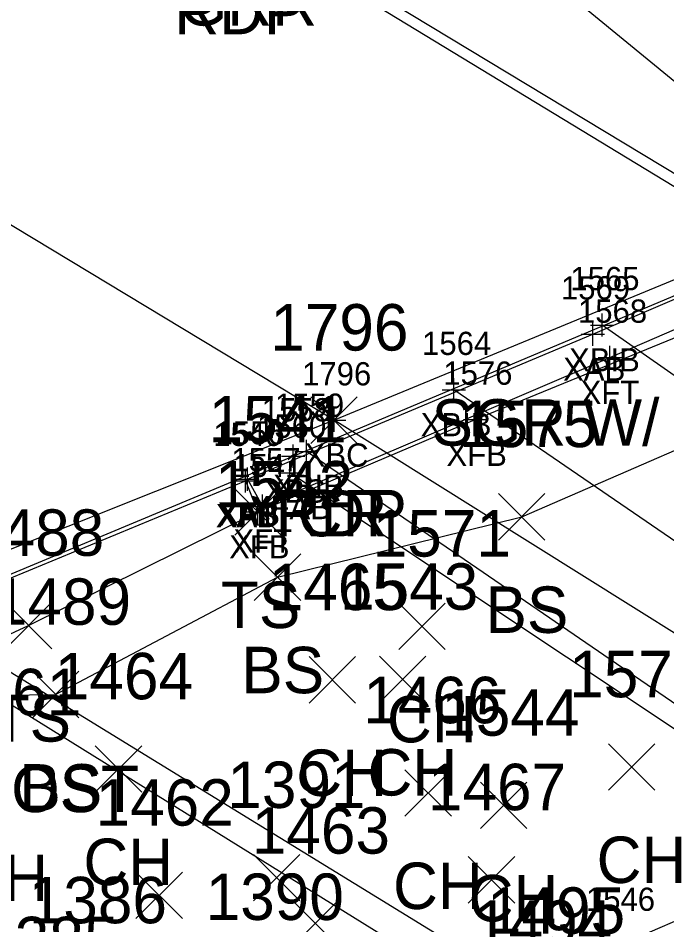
# Model space of a CAD drawing. Extents: x 1537342 to 1542195, y 163002 to 168596.
# Drawn here: x 1541772.7 to 1541800.63, y 163314.55 to 163353.59 of the extents above; entities that cross this region are included whole.
import ezdxf

# ---------------------------------------------------------------- set-up
doc = ezdxf.new("R2010")
doc.units = 0
for name, color, linetype in [('B_A', 7, 'Continuous'), ('B_I', 7, 'Continuous'), ('B_TIC', 7, 'Continuous'), ('BB', 7, 'Continuous'), ('BELB', 7, 'Continuous'), ('BF', 7, 'Continuous'), ('BFT', 7, 'Continuous'), ('BSE', 7, 'Continuous'), ('BSUBM', 7, 'Continuous'), ('L_A', 7, 'Continuous'), ('L_I', 7, 'Continuous'), ('L_TIC', 7, 'Continuous'), ('LELB', 7, 'Continuous'), ('P_A', 7, 'Continuous'), ('P_I', 7, 'Continuous'), ('P_TIC', 7, 'Continuous'), ('PET', 7, 'Continuous'), ('PRC', 7, 'Continuous'), ('R_A', 7, 'Continuous'), ('R_C', 7, 'Continuous'), ('R_I', 7, 'Continuous'), ('RGR', 7, 'Continuous')]:
    doc.layers.add(name, color=color, linetype=linetype)

msp = doc.modelspace()

# ---------------------------------------------------------------- linework, layer by layer
at = {"layer": 'B_TIC'}
for p, q in [((1541797.852, 163340.377), (1541797.927, 163340.377)), ((1541797.448, 163339.977), (1541797.523, 163339.977)), ((1541798.179, 163338.976), (1541798.254, 163338.976)), ((1541791.466, 163337.587), (1541791.542, 163337.587)), ((1541786.307, 163336.277), (1541786.383, 163336.277)), ((1541792.385, 163336.306), (1541792.461, 163336.306)), ((1541784.545, 163334.727), (1541784.62, 163334.727)), ((1541785.116, 163334.926), (1541785.192, 163334.926)), ((1541784.408, 163334.015), (1541784.483, 163334.015)), ((1541782.496, 163333.668), (1541782.572, 163333.668)), ((1541782.496, 163333.668), (1541782.572, 163333.668)), ((1541782.585, 163333.735), (1541782.66, 163333.735)), ((1541782.585, 163333.735), (1541782.66, 163333.735)), ((1541783.03, 163332.327), (1541783.106, 163332.327)), ((1541783.233, 163332.577), (1541783.308, 163332.577))]:
    msp.add_line(p, q, dxfattribs=at)
for points in [[(1541797.848, 163339.877), (1541797.848, 163340.877)], [(1541797.348, 163340.377), (1541798.348, 163340.377)], [(1541797.444, 163339.477), (1541797.444, 163340.477)], [(1541796.944, 163339.977), (1541797.944, 163339.977)], [(1541798.175, 163338.476), (1541798.175, 163339.476)], [(1541797.675, 163338.976), (1541798.675, 163338.976)], [(1541791.463, 163337.087), (1541791.463, 163338.087)], [(1541790.963, 163337.587), (1541791.963, 163337.587)], [(1541786.304, 163335.777), (1541786.304, 163336.777)], [(1541792.382, 163335.806), (1541792.382, 163336.806)], [(1541785.804, 163336.277), (1541786.804, 163336.277)], [(1541791.882, 163336.306), (1541792.882, 163336.306)], [(1541784.541, 163334.227), (1541784.541, 163335.227)], [(1541785.113, 163334.426), (1541785.113, 163335.426)], [(1541784.041, 163334.727), (1541785.041, 163334.727)], [(1541784.613, 163334.926), (1541785.613, 163334.926)], [(1541784.404, 163333.515), (1541784.404, 163334.515)], [(1541782.493, 163333.168), (1541782.493, 163334.168)], [(1541782.493, 163333.168), (1541782.493, 163334.168)], [(1541782.581, 163333.235), (1541782.581, 163334.235)], [(1541782.581, 163333.235), (1541782.581, 163334.235)], [(1541783.904, 163334.015), (1541784.904, 163334.015)], [(1541781.993, 163333.668), (1541782.993, 163333.668)], [(1541781.993, 163333.668), (1541782.993, 163333.668)], [(1541782.081, 163333.735), (1541783.081, 163333.735)], [(1541782.081, 163333.735), (1541783.081, 163333.735)], [(1541783.027, 163331.827), (1541783.027, 163332.827)], [(1541783.229, 163332.077), (1541783.229, 163333.077)], [(1541782.527, 163332.327), (1541783.527, 163332.327)], [(1541782.729, 163332.577), (1541783.729, 163332.577)]]:
    msp.add_lwpolyline(points, dxfattribs=at)
at = {"layer": 'BB'}
for points in [[(1541821.778, 163323.627), (1541797.848, 163340.377)], [(1541815.707, 163320.976), (1541791.463, 163337.587)], [(1541809.434, 163318.27), (1541785.113, 163334.926)]]:
    msp.add_lwpolyline(points, dxfattribs=at)
at = {"layer": 'BELB'}
for points in [[(1541814.195, 163318.824), (1541786.304, 163336.277)], [(1541795.579, 163311.161), (1541767.135, 163328.632)]]:
    msp.add_lwpolyline(points, dxfattribs=at)
at = {"layer": 'BF'}
for points in [[(1541808.217, 163318.129), (1541784.404, 163334.015)], [(1541767.818, 163326.884), (1541792.553, 163311.514)]]:
    msp.add_lwpolyline(points, dxfattribs=at)
at = {"layer": 'BFT'}
for points in [[(1541782.493, 163333.668), (1541783.027, 163332.327), (1541792.382, 163336.306), (1541803.266, 163340.778), (1541807.821, 163342.807), (1541807.794, 163344.415)], [(1541782.581, 163333.735), (1541783.229, 163332.577), (1541798.175, 163338.976), (1541807.692, 163343.098), (1541807.794, 163344.415)]]:
    msp.add_lwpolyline(points, dxfattribs=at)
at = {"layer": 'BSE'}
msp.add_lwpolyline([(1541766.859, 163327.35), (1541784.541, 163334.727), (1541807.069, 163344.219)], dxfattribs=at)
at = {"layer": 'BSUBM'}
for points in [[(1541753.675, 163328.14), (1541753.474, 163327.4), (1541754.806, 163327.195), (1541759.413, 163327.06), (1541763.565, 163326.932), (1541765.907, 163326.789), (1541769.576, 163328.325), (1541782.493, 163333.668), (1541782.581, 163333.735), (1541797.444, 163339.977), (1541807.794, 163344.415), (1541807.593, 163352.289)], [(1541792.632, 163303.617), (1541790.864, 163303.749), (1541791.033, 163307.198), (1541791.076, 163308.949), (1541791.185, 163310.492), (1541798.521, 163313.65), (1541805.481, 163316.659), (1541805.688, 163316.76), (1541820.303, 163323.059), (1541830.941, 163327.84), (1541831.268, 163327.91)]]:
    msp.add_lwpolyline(points, dxfattribs=at)
at = {"layer": 'L_TIC'}
for points in [[(1541782.027, 163331.327), (1541784.027, 163333.327)], [(1541784.027, 163331.327), (1541782.027, 163333.327)], [(1541793.382, 163331.118), (1541795.382, 163333.118)], [(1541795.382, 163331.118), (1541793.382, 163333.118)], [(1541782.87, 163328.52), (1541784.87, 163330.52)], [(1541784.87, 163328.52), (1541782.87, 163330.52)], [(1541772.155, 163326.437), (1541774.155, 163328.437)], [(1541774.155, 163326.437), (1541772.155, 163328.437)], [(1541789.093, 163326.405), (1541791.093, 163328.405)], [(1541791.093, 163326.405), (1541789.093, 163328.405)], [(1541785.231, 163324.097), (1541787.231, 163326.097)], [(1541787.231, 163324.097), (1541785.231, 163326.097)], [(1541788.256, 163324.115), (1541790.256, 163326.115)], [(1541790.256, 163324.115), (1541788.256, 163326.115)], [(1541773.317, 163323.466), (1541775.317, 163325.466)], [(1541775.317, 163323.466), (1541773.317, 163325.466)], [(1541776.024, 163320.26), (1541778.024, 163322.26)], [(1541778.024, 163320.26), (1541776.024, 163322.26)], [(1541798.119, 163320.348), (1541800.119, 163322.348)], [(1541800.119, 163320.348), (1541798.119, 163322.348)], [(1541789.354, 163319.228), (1541791.354, 163321.228)], [(1541791.354, 163319.228), (1541789.354, 163321.228)], [(1541792.61, 163318.692), (1541794.61, 163320.692)], [(1541794.61, 163318.692), (1541792.61, 163320.692)], [(1541782.834, 163315.579), (1541784.834, 163317.579)], [(1541784.834, 163315.579), (1541782.834, 163317.579)], [(1541792.084, 163315.483), (1541794.084, 163317.483)], [(1541794.084, 163315.483), (1541792.084, 163317.483)], [(1541777.778, 163314.819), (1541779.778, 163316.819)], [(1541779.778, 163314.819), (1541777.778, 163316.819)], [(1541784.502, 163313.612), (1541786.502, 163315.612)], [(1541786.502, 163313.612), (1541784.502, 163315.612)]]:
    msp.add_lwpolyline(points, dxfattribs=at)
at = {"layer": 'LELB'}
for points in [[(1541806.46, 163346.352), (1541770.849, 163375.533), (1541766.113, 163382.325), (1541753.114, 163384.462), (1541712.964, 163403.647), (1541689.279, 163419.489), (1541645.558, 163455.193), (1541611.137, 163481.599), (1541585.037, 163504.654)], [(1541680.476, 163291.861), (1541699.97, 163293.9), (1541717.141, 163294.135), (1541730.523, 163297.571), (1541741.654, 163302.345), (1541748.176, 163305.385), (1541748.078, 163309.08), (1541755.23, 163315.369), (1541766.506, 163324.36), (1541774.317, 163324.466), (1541783.87, 163329.52), (1541794.382, 163332.118), (1541806.545, 163337.396), (1541818.819, 163343.081), (1541839.231, 163350.559), (1541851.311, 163354.645), (1541860.204, 163362.664), (1541879.488, 163366.965), (1541895.128, 163366.199), (1541914.254, 163372.826), (1541910.846, 163375.465), (1541893.701, 163387.218), (1541872.662, 163402.005), (1541849.049, 163411.834)], [(1541766.506, 163324.36), (1541773.155, 163327.437), (1541783.027, 163332.327)]]:
    msp.add_lwpolyline(points, dxfattribs=at)
at = {"layer": 'P_TIC'}
for points in [[(1541785.304, 163335.277), (1541787.304, 163337.277)], [(1541787.304, 163335.277), (1541785.304, 163337.277)], [(1541785.304, 163335.277), (1541787.304, 163337.277)], [(1541787.304, 163335.277), (1541785.304, 163337.277)]]:
    msp.add_lwpolyline(points, dxfattribs=at)
at = {"layer": 'PET'}
for points in [[(1541804.882, 163343.94), (1541781.937, 163357.897), (1541762.271, 163369.13), (1541719.068, 163393.382), (1541702.013, 163402.189), (1541685.469, 163410.812), (1541633.416, 163436.219), (1541598.663, 163451.943), (1541573.75, 163461.19), (1541557.97, 163467.971)], [(1541804.882, 163343.94), (1541786.304, 163336.277), (1541767.135, 163328.632), (1541744.371, 163342.884), (1541704.795, 163365.128), (1541670.451, 163382.893), (1541617.103, 163408.356), (1541585.571, 163422.3), (1541550.232, 163436.7), (1541542.2, 163439.813)]]:
    msp.add_lwpolyline(points, dxfattribs=at)
at = {"layer": 'PRC'}
msp.add_lwpolyline([(1541786.304, 163336.277), (1541753.026, 163356.379), (1541711.826, 163379.06), (1541677.625, 163397.186), (1541623.384, 163422.529), (1541592.115, 163436.736), (1541548.189, 163454.577)], dxfattribs=at)
at = {"layer": 'RGR'}
msp.add_lwpolyline([(1541805.439, 163344.183), (1541782.138, 163358.273), (1541763.753, 163370.726), (1541749.181, 163380.81)], dxfattribs=at)

# ---------------------------------------------------------------- texts
at = {"layer": 'B_A'}
for s, p in [('XBIB', (1541796.419, 163338.377)), ('XAB', (1541796.165, 163337.977)), ('XFT', (1541796.919, 163336.976)), ('XBIB', (1541790.034, 163335.587)), ('XBC', (1541785.04, 163334.277)), ('XFB', (1541791.142, 163334.306)), ('XBIB', (1541783.684, 163332.926)), ('XBS', (1541783.281, 163332.727)), ('XAB', (1541781.302, 163331.735)), ('XFT', (1541781.325, 163331.735)), ('XFAB', (1541782.676, 163332.015)), ('XAB', (1541781.213, 163331.668)), ('XFB', (1541781.252, 163331.668)), ('XFT', (1541781.973, 163330.577)), ('XFB', (1541781.786, 163330.327))]:
    msp.add_text(s, height=1, dxfattribs=at).set_placement(p)
at = {"layer": 'B_I'}
for s, p in [('1565', (1541796.478, 163341.877)), ('1569', (1541796.071, 163341.477)), ('1568', (1541796.805, 163340.476)), ('1564', (1541790.093, 163339.087)), ('1796', (1541784.93, 163337.777)), ('1576', (1541791.008, 163337.806)), ('1559', (1541783.763, 163336.426)), ('1558', (1541783.195, 163336.227)), ('1556', (1541781.207, 163335.235)), ('1556', (1541781.207, 163335.235)), ('1560', (1541782.991, 163335.515)), ('1540', (1541781.103, 163335.168)), ('1540', (1541781.103, 163335.168)), ('1557', (1541781.883, 163334.077)), ('1541', (1541781.964, 163333.827)), ('1546', (1541797.147, 163315.15))]:
    msp.add_text(s, height=1, dxfattribs=at).set_placement(p)
at = {"layer": 'L_A'}
for s, p in [('TS', (1541781.436, 163327.327)), ('BS', (1541792.823, 163327.118)), ('BS', (1541782.311, 163324.52)), ('TS', (1541771.564, 163322.437)), ('CH', (1541788.581, 163322.405)), ('CH', (1541784.72, 163320.097)), ('CH', (1541787.744, 163320.115)), ('BS', (1541772.758, 163319.466)), ('CH', (1541775.512, 163316.26)), ('CH', (1541797.607, 163316.348)), ('CH', (1541770.134, 163315.572)), ('CH', (1541788.843, 163315.228)), ('CH', (1541792.098, 163314.692))]:
    msp.add_text(s, height=2, dxfattribs=at).set_placement(p)
at = {"layer": 'L_I'}
for s, p in [('1541', (1541780.901, 163335.327)), ('1575', (1541791.69, 163335.118)), ('1542', (1541781.178, 163332.52)), ('1488', (1541770.462, 163330.437)), ('1571', (1541787.967, 163330.405)), ('1465', (1541783.491, 163328.097)), ('1543', (1541786.563, 163328.115)), ('1489', (1541771.616, 163327.466)), ('1464', (1541774.284, 163324.26)), ('1572', (1541796.426, 163324.348)), ('1461', (1541769.472, 163323.572)), ('1466', (1541787.559, 163323.228)), ('1544', (1541790.917, 163322.692)), ('1391', (1541781.709, 163319.579)), ('1467', (1541790.344, 163319.483)), ('1462', (1541776.038, 163318.819)), ('1463', (1541782.762, 163317.612)), ('1390', (1541780.777, 163314.756)), ('1386', (1541773.162, 163314.614)), ('1385', (1541771.07, 163312.895))]:
    msp.add_text(s, height=2, dxfattribs=at).set_placement(p)
at = {"layer": 'P_A'}
for s, p in [('RDP', (1541779.425, 163352.897)), ('RDP', (1541783.792, 163331.277)), ('CR', (1541784.737, 163331.277))]:
    msp.add_text(s, height=2, dxfattribs=at).set_placement(p)
at = {"layer": 'P_I'}
for s, p in [('1796', (1541783.556, 163339.277)), ('1796', (1541783.556, 163339.277)), ('1495', (1541792.886, 163314.161))]:
    msp.add_text(s, height=2, dxfattribs=at).set_placement(p)
at = {"layer": 'R_A'}
msp.add_text('GRR', height=2, dxfattribs=at).set_placement((1541779.626, 163353.273))
at = {"layer": 'R_C'}
for s, p in [('SGR W/ STEELPOST', (1541790.503, 163335.183)), ('SGR W/ STEEL POST', (1541750.86, 163319.399))]:
    msp.add_text(s, height=2, dxfattribs=at).set_placement(p)
at = {"layer": 'R_I'}
msp.add_text('1494', height=2, dxfattribs=at).set_placement((1541792.332, 163313.604))

doc.saveas('drawing.dxf')
